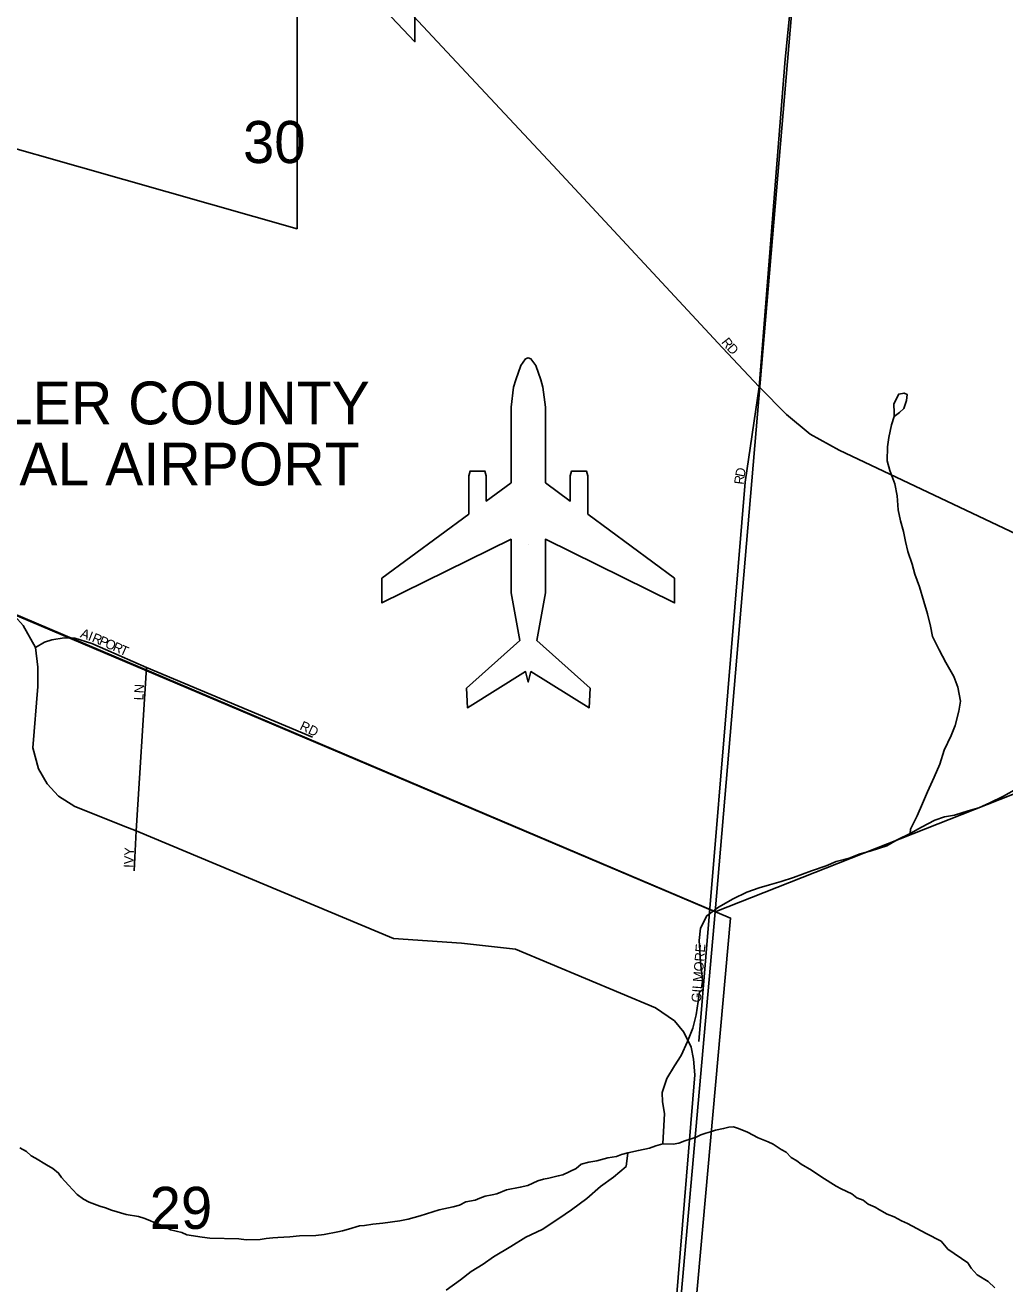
# Model space of a CAD drawing. Extents: x 1310247 to 1552180, y 377264 to 706493.
# Drawn here: x 1394083 to 1399232, y 499946 to 506561 of the extents above; entities that cross this region are included whole.
import ezdxf

# ---------------------------------------------------------------- set-up
doc = ezdxf.new("R2010")
doc.units = 0
for name, color, linetype in [('GM_X_Airport_Class_2', 7, 'Continuous'), ('GM_X_Airport_Location_Class_2', 7, 'Continuous'), ('GM_X_Airport_Text_Class_2', 7, 'Continuous'), ('GM_X_City_Street', 7, 'Continuous'), ('GM_X_City_Street_Text', 7, 'Continuous'), ('GM_X_Corporation', 7, 'Continuous'), ('GM_X_Minor_River', 7, 'Continuous'), ('GM_X_Rail_Line_Text', 7, 'Continuous'), ('GM_X_Section', 7, 'Continuous'), ('GM_X_Section_Text', 7, 'Continuous')]:
    doc.layers.add(name, color=color, linetype=linetype)

msp = doc.modelspace()

# ---------------------------------------------------------------- linework, layer by layer
at = {"layer": 'GM_X_Airport_Class_2'}
msp.add_lwpolyline([(1396414.6, 503991.2), (1395958.2, 503653.7), (1395958.2, 503524.2), (1396637.2, 503858.8), (1396637.2, 503577), (1396682.3, 503327.6), (1396402.9, 503077), (1396407.3, 502973.9), (1396713.3, 503163.5), (1396727.4, 503108), (1396741.5, 503163.5), (1397047.6, 502973.9), (1397052, 503077.1), (1396772.6, 503327.6), (1396817.6, 503577), (1396817.6, 503858.8), (1397496.6, 503524.2), (1397496.6, 503653.7), (1397040.2, 503991.2), (1397040.2, 504192.7), (1397033.2, 504217.2), (1396955.4, 504217.2), (1396948.4, 504192.7), (1396948.4, 504059.2), (1396817.6, 504155.8), (1396817.6, 504155.8), (1396817.6, 504553.7), (1396804.5, 504658.9), (1396793.5, 504696.4), (1396766.6, 504773), (1396741.7, 504807.1), (1396727.4, 504813), (1396713.2, 504807.1), (1396688.3, 504773), (1396661.3, 504696.4), (1396650.4, 504658.9), (1396637.2, 504553.7), (1396637.2, 504155.8), (1396506.5, 504059.2), (1396506.5, 504192.7), (1396499.5, 504217.2), (1396421.7, 504217.2), (1396414.6, 504192.7)], close=True, dxfattribs=at)
at = {"layer": 'GM_X_Airport_Location_Class_2'}
msp.add_line((1396727.4, 503830.4), (1396727.4, 503830.4), dxfattribs=at)
at = {"layer": 'GM_X_City_Street'}
for points in [[(1397940.3, 504660.6), (1398077.8, 506381.3), (1398160, 507202.6), (1398274.4, 508696.9)], [(1395641.4, 507129.2), (1395744, 507016.4), (1396857.3, 505825.3), (1397748.4, 504865), (1397940.3, 504660.6), (1398084.2, 504515.2), (1398209.3, 504411.8), (1398360.9, 504327.9), (1400655.3, 503241.7), (1401689.8, 502759.8), (1401706.8, 502751.7)], [(1397680.7, 501897.9), (1397776.9, 503056.7), (1397867.9, 504159.5), (1397940.3, 504660.6)], [(1392566, 504088.3), (1392648.5, 504063.3), (1392691.4, 504047.7), (1392813.5, 503997.1), (1393501.1, 503703.2), (1393897.4, 503541.4), (1393968.8, 503502.3), (1394027.8, 503455.4), (1394071.9, 503405.1), (1394136.9, 503290.4), (1394149.6, 503186), (1394149.6, 503085.3), (1394124.1, 502763), (1394152.2, 502652.1), (1394198, 502574.5), (1394257.9, 502509.5), (1394343.3, 502454.7), (1394621.3, 502344.7)], [(1394136.9, 503290.4), (1394183.9, 503318.3), (1394222.4, 503330.4), (1394288.3, 503341), (1394344.7, 503338.9)], [(1394344.7, 503338.9), (1394433.8, 503310.4), (1394720.1, 503184.4), (1395593.8, 502819.5)], [(1394655.3, 502116.8), (1394666, 502327), (1394720.1, 503184.4)], [(1394621.3, 502344.7), (1394666, 502327), (1396018.9, 501761.5), (1396377.2, 501736.3), (1396660.1, 501704.9), (1397395.6, 501396.8), (1397496.1, 501327.6), (1397544.9, 501267.9), (1397584.1, 501189.3), (1397595.2, 501126.4), (1397603, 501044.7)], [(1397624.4, 501220), (1397680.7, 501897.9)], [(1397505.4, 499851.6), (1397603, 501044.7)]]:
    msp.add_lwpolyline(points, dxfattribs=at)
at = {"layer": 'GM_X_Corporation'}
for points in [[(1392764.8, 506271.6), (1395512.5, 505490.6), (1395512.7, 507127.4), (1396132, 506473.7), (1396132.1, 506909.5)], [(1390471.8, 499365.5), (1390574.6, 500695.1), (1391069.6, 500631.1), (1391079, 500799.1), (1391136.1, 501130.9), (1391182, 501363.3), (1391210.6, 501512.5), (1391211.3, 501579.6), (1391202.6, 501659.9), (1391184.7, 501753.6), (1390962.5, 502367.5), (1390691.9, 503067.7), (1390985.9, 503152.1), (1390330, 504285.9), (1392657.6, 504046.7), (1397790.8, 501867.9), (1397344, 496894.2)], [(1397344, 496894.2), (1397790.8, 501867.9), (1392657.6, 504046.7), (1390330, 504285.9), (1390985.9, 503152.1), (1390691.9, 503067.7), (1390962.5, 502367.5), (1391184.7, 501753.6), (1391202.6, 501659.9), (1391211.3, 501579.6), (1391210.6, 501512.5), (1391182, 501363.3), (1391136.1, 501130.9), (1391079, 500799.1), (1391069.6, 500631.1), (1390574.6, 500695.1), (1390471.8, 499365.5)]]:
    msp.add_lwpolyline(points, dxfattribs=at)
at = {"layer": 'GM_X_Minor_River'}
for points in [[(1398651.5, 504503.9), (1398678.2, 504525.3), (1398700.8, 504546.8), (1398716, 504588.5), (1398718.9, 504620.6), (1398703, 504627.1), (1398674.8, 504621.8), (1398649.3, 504570.2)], [(1398649.3, 504570.2), (1398650, 504524), (1398651.5, 504503.9)], [(1398636.2, 504460.1), (1398651.5, 504503.9)], [(1398735.6, 502313.5), (1398736.2, 502335.6), (1398772.3, 502404.9), (1398800.1, 502470.5), (1398825.9, 502532.1), (1398860.2, 502609.5), (1398890.1, 502677), (1398914.2, 502750.7), (1398950.5, 502828.1), (1398972, 502879.7), (1398990.1, 502955.6), (1398999.6, 503007.6), (1398985.6, 503082.3), (1398965, 503137.1), (1398922.9, 503210.6), (1398886.6, 503277.9), (1398852.4, 503347.1), (1398841.9, 503401.7), (1398825.6, 503466.4), (1398807.3, 503531.2), (1398783.3, 503608.2), (1398759.1, 503675.1), (1398744.5, 503727.8), (1398722.2, 503794.7), (1398709.6, 503847.3), (1398699.1, 503899.8), (1398684.6, 503956.5), (1398672.1, 504013.1), (1398666.1, 504087.6), (1398653.8, 504150.2), (1398627.6, 504221.2), (1398613, 504271.8), (1398615, 504344.1), (1398622.4, 504394.2), (1398636.2, 504460.1)], [(1397647.4, 501492.9), (1397641.3, 501561.4), (1397633.2, 501634), (1397629, 501698.4), (1397626.4, 501750.7), (1397632.2, 501814.8), (1397666.1, 501880.2), (1397727.5, 501924.8), (1397805, 501968.9), (1397876.2, 502005.2), (1397941.1, 502027.5), (1397995.7, 502042.1), (1398056.4, 502060.6), (1398121.2, 502080.9), (1398216.5, 502116.5), (1398293.4, 502142.6), (1398346.2, 502165.3), (1398415, 502183.5), (1398471.8, 502206.1), (1398524.4, 502220.7), (1398611.4, 502248.5), (1398666.4, 502279.2), (1398735.6, 502313.5), (1398794.7, 502346), (1398863.9, 502382.3), (1398914.6, 502401.1), (1398967, 502409.7), (1399039.9, 502431.8), (1399096.5, 502448.4), (1399153.4, 502473), (1399224.6, 502509.2), (1399281.7, 502539.8)], [(1397647.4, 501492.9), (1397627, 501481.4), (1397619.6, 501429.4), (1397609.6, 501359.3), (1397591.6, 501289.5), (1397563.6, 501219.9), (1397531.5, 501146.5), (1397495.9, 501091.2), (1397455.9, 501025.9), (1397431.8, 500952.2), (1397432.4, 500902), (1397442.8, 500841.4), (1397434.1, 500681.6)], [(1398720.7, 500262.8), (1398688.9, 500277.7), (1398651.3, 500298.7), (1398613.5, 500311.8), (1398573.9, 500334.9), (1398550.2, 500349.6), (1398514.5, 500364.5), (1398486.9, 500385.3), (1398455.1, 500398.2), (1398427.5, 500419), (1398372, 500444.5), (1398346.2, 500459.3), (1398271.2, 500507.4), (1398215.9, 500543), (1398162.5, 500574.5), (1398138.9, 500593.2), (1398109.2, 500610), (1398083.8, 500638.8), (1398056, 500651.5), (1398014.6, 500680.7), (1397988.8, 500691.5), (1397935.1, 500712.9), (1397879.7, 500742.5), (1397832, 500761.8), (1397806.1, 500770.5), (1397782, 500769.1), (1397753.6, 500761.8), (1397711.2, 500752.8), (1397684.9, 500745.5), (1397660.6, 500738.1), (1397634.3, 500728.7), (1397609.8, 500717.3), (1397583.5, 500707.9), (1397551, 500696.7), (1397518.6, 500685.5), (1397488.3, 500680.2), (1397434.1, 500681.6), (1397397.7, 500670.5), (1397365.3, 500659.3), (1397306.7, 500646.8), (1397250.1, 500634.2), (1397217.7, 500624.9), (1397191.4, 500615.6), (1397145, 500608.8), (1397088.3, 500592.1), (1397045.9, 500585.2), (1397005.5, 500574.2), (1396978.8, 500552.8), (1396909.6, 500518.4), (1396885.3, 500513), (1396834.8, 500502.2), (1396806.6, 500496.9), (1396778.2, 500487.6), (1396725.3, 500462.9), (1396684.9, 500453.9), (1396612.2, 500439.7), (1396561.5, 500418.9), (1396537.2, 500413.5), (1396500.9, 500406.4), (1396472.5, 500397.1), (1396448.1, 500385.7), (1396399.7, 500376.9), (1396365.1, 500359.7), (1396332.7, 500350.5), (1396259.9, 500334.3), (1396158.7, 500302.7), (1396096, 500286.3), (1396051.5, 500277.4), (1395962.8, 500265.6), (1395910.4, 500258.9), (1395866.1, 500252), (1395839.9, 500250.7), (1395783.2, 500234.1), (1395750.9, 500224.8), (1395726.6, 500219.5), (1395653.9, 500205.3), (1395611.6, 500200.3), (1395525.2, 500198.5), (1395474.8, 500193.8), (1395410.4, 500189.4), (1395384.3, 500188.1), (1395350.1, 500185), (1395317.8, 500179.8), (1395245.4, 500177.6), (1395205.4, 500182.7), (1395052.8, 500186.6), (1395012.8, 500191.6), (1394932.8, 500203.8), (1394907, 500216.5), (1394847.1, 500230.1), (1394807.5, 500251.2), (1394761.7, 500268.4), (1394737.9, 500279.1), (1394706.1, 500292), (1394678.2, 500300.7), (1394614.2, 500310.4), (1394536.4, 500332.5), (1394504.6, 500345.3), (1394474.7, 500354.2), (1394419.1, 500375.7), (1394389.3, 500390.5)], [(1394389.3, 500390.5), (1394355.8, 500415.5), (1394311, 500464.8), (1394273.8, 500504), (1394258.4, 500528.5), (1394228.9, 500551.3), (1394195.3, 500572.3), (1394137.9, 500605.9), (1394114.2, 500618.6), (1394090.6, 500641.3), (1394055, 500660.3)], [(1397250.1, 500634.2), (1397242.5, 500563.5), (1397174.7, 500507.1), (1397107.1, 500456.7), (1397035.2, 500394.3), (1396955.2, 500334.2), (1396887.8, 500289.8), (1396799.9, 500231.9), (1396714.5, 500192), (1396634.9, 500141.9), (1396545.1, 500088.1), (1396489.9, 500049.4), (1396426.6, 500010.9), (1396371.2, 499966.2), (1396295.4, 499912)], [(1399179.8, 499925.6), (1399144.5, 499958.6), (1399087.2, 499994.2), (1399056, 500029.2), (1399038.6, 500055.8), (1398932.1, 500128.8), (1398897, 500169.9), (1398819.7, 500210), (1398720.7, 500262.8)]]:
    msp.add_lwpolyline(points, dxfattribs=at)
at = {"layer": 'GM_X_Section'}
for points in [[(1393070, 509536.8), (1398289.5, 508719.6), (1397709.1, 501901.1), (1392551, 504087.3)], [(1398704.7, 508684.1), (1403401, 509422.4), (1402970.8, 503976.8), (1397709.1, 501901.1), (1398289.5, 508719.6)], [(1392551, 504087.3), (1397709.1, 501901.1), (1397269.5, 496943), (1392089.7, 498619.6)], [(1397709.1, 501901.1), (1402970.8, 503976.8), (1402585.9, 498525.4), (1397269.5, 496943)]]:
    msp.add_lwpolyline(points, close=True, dxfattribs=at)

# ---------------------------------------------------------------- texts
at = {"layer": 'GM_X_Airport_Text_Class_2'}
for s, p in [('BUTLER COUNTY', (1393353.6, 504462.8)), ('REGIONAL AIRPORT', (1392865.2, 504141.6))]:
    msp.add_text(s, height=225, rotation=0.00001, dxfattribs=at).set_placement(p)
at = {"layer": 'GM_X_City_Street_Text'}
for s, rotation, p in [('R', 307.75146, (1397739.9, 504894.1)), ('D', 314.38791, (1397768.3, 504858.1)), ('D', 79.03728, (1397863.4, 504182.9)), ('R', 82.69423, (1397858.5, 504144.4)), ('A', 339.37361, (1394368.9, 503345.3)), ('I', 339.03467, (1394410, 503329.8)), ('R', 337.42964, (1394430.2, 503322.1)), ('P', 336.50906, (1394466.6, 503307)), ('O', 336.44697, (1394498.8, 503293)), ('R', 336.44431, (1394539.2, 503275.4)), ('T', 336.4445, (1394575.5, 503259.5)), ('LN', 86.98872, (1394703.8, 503011.4)), ('RD', 334.80074, (1395522.4, 502861)), ('IVY', 87.70624, (1394651, 502131.3)), ('GILMORE', 85.46296, (1397634.2, 501423.2))]:
    msp.add_text(s, height=50, rotation=rotation, dxfattribs=at).set_placement(p)
at = {"layer": 'GM_X_Rail_Line_Text'}
msp.add_text('Transportation,', height=299, rotation=313.9502, dxfattribs=at).set_placement((1392305, 500842.4))
at = {"layer": 'GM_X_Section_Text'}
for s, p in [('30', (1395228, 505836)), ('29', (1394737.4, 500234.8))]:
    msp.add_text(s, height=221, rotation=0.00001, dxfattribs=at).set_placement(p)

doc.saveas('drawing.dxf')
